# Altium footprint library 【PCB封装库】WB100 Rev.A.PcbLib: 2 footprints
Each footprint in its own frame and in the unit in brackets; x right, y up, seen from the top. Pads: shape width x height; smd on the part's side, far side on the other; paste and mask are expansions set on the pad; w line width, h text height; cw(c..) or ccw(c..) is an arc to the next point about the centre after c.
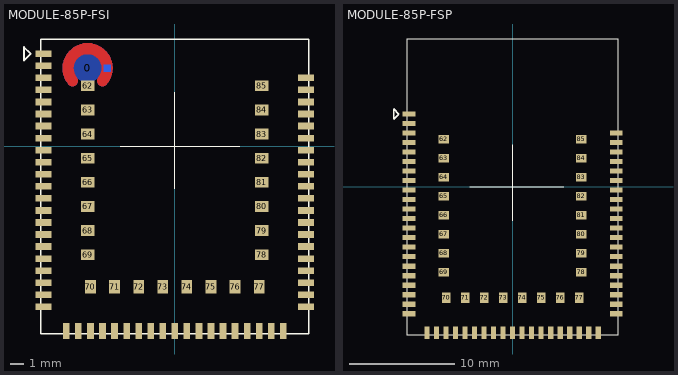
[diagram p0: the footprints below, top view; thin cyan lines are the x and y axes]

## MODULE-85P-FSI [mm]
pads (87):
  round 1.016 on Mech13 paste-0.508 mask+0.152: 0(-6.512,5.818)
  rect 1.2x0.5 smd: 1(-9.8,6.9) 2(-9.8,6) 3(-9.8,5.1) 4(-9.8,4.2) 5(-9.8,3.3) 6(-9.8,2.4) 7(-9.8,1.5) 8(-9.8,0.6) 9(-9.8,-0.3) 10(-9.8,-1.2) 11(-9.8,-2.1) 12(-9.8,-3) 13(-9.8,-3.9) 14(-9.8,-4.8) 15(-9.8,-5.7) 16(-9.8,-6.6) 17(-9.8,-7.5) 18(-9.8,-8.4) 19(-9.8,-9.3) 20(-9.8,-10.2) 21(-9.8,-11.1) 22(-9.8,-12) 42(9.8,-12) 43(9.8,-11.1) 44(9.8,-10.2) 45(9.8,-9.3) 46(9.8,-8.4) 47(9.8,-7.5) 48(9.8,-6.6) 49(9.8,-5.7) 50(9.8,-4.8) 51(9.8,-3.9) 52(9.8,-3) 53(9.8,-2.1) 54(9.8,-1.2) 55(9.8,-0.3) 56(9.8,0.6) 57(9.8,1.5) 58(9.8,2.4) 59(9.8,3.3) 60(9.8,4.2) 61(9.8,5.1)
  rect 0.508x0.508 smd far side paste-0.254: 2(-5.051,5.818)
  rect 0.5x1.2 smd: 23(-8.1,-13.8) 24(-7.2,-13.8) 25(-6.3,-13.8) 26(-5.4,-13.8) 27(-4.5,-13.8) 28(-3.6,-13.8) 29(-2.7,-13.8) 30(-1.8,-13.8) 31(-0.9,-13.8) 32(0,-13.8) 33(0.9,-13.8) 34(1.8,-13.8) 35(2.7,-13.8) 36(3.6,-13.8) 37(4.5,-13.8) 38(5.4,-13.8) 39(6.3,-13.8) 40(7.2,-13.8) 41(8.1,-13.8)
  rect 1x0.8 smd: 62(-6.5,4.5) 63(-6.5,2.7) 64(-6.5,0.9) 65(-6.5,-0.9) 66(-6.5,-2.7) 67(-6.5,-4.5) 68(-6.5,-6.3) 69(-6.5,-8.1) 78(6.5,-8.1) 79(6.5,-6.3) 80(6.5,-4.5) 81(6.5,-2.7) 82(6.5,-0.9) 83(6.5,0.9) 84(6.5,2.7) 85(6.5,4.5)
  rect 0.8x1 smd: 70(-6.3,-10.5) 71(-4.5,-10.5) 72(-2.7,-10.5) 73(-0.9,-10.5) 74(0.9,-10.5) 75(2.7,-10.5) 76(4.5,-10.5) 77(6.3,-10.5)
Top Layer:
  lines w0.838: -7.631,4.879 cw(c-6.512,5.818) -5.393,4.879
Bottom Layer:
  pour cut-out: -7.553,5.818 -7.553,5.921 -7.513,6.122 -7.435,6.311 -7.321,6.482 -7.176,6.627 -7.005,6.741 -6.816,6.819 -6.614,6.859 -6.512,6.859 -6.409,6.859 -6.208,6.819 -6.019,6.741 -5.848,6.627 -5.703,6.482 -5.589,6.311 -5.51,6.122 -5.47,5.921 -5.47,5.818 -5.47,5.716 -5.51,5.514 -5.589,5.325 -5.703,5.154 -5.848,5.009 -6.019,4.895 -6.208,4.817 -6.409,4.777 -6.512,4.777 -6.614,4.777 -6.816,4.817 -7.005,4.895 -7.176,5.009 -7.321,5.154 -7.435,5.325 -7.513,5.514 -7.553,5.716
  lines w0.838: -7.631,4.879 cw(c-6.512,5.818) -5.393,4.879
Top Overlay:
  lines w0.01: -4.059,0 4.846,0 ; 0,-3.195 0,4.011
  lines w0.1: -10,-14 10,-14
  lines w0.102: -10,-14 10,-14 10,8 -10,8 -10,-14
  lines w0.127: -11.268,6.387 -11.268,7.403 -10.76,6.895 -11.268,6.387

## MODULE-85P-FSP [mm]
pads (85):
  rect 1.2x0.5 smd mask-0.25: 1(-9.8,6.9) 2(-9.8,6) 3(-9.8,5.1) 4(-9.8,4.2) 5(-9.8,3.3) 6(-9.8,2.4) 7(-9.8,1.5) 8(-9.8,0.6) 9(-9.8,-0.3) 10(-9.8,-1.2) 11(-9.8,-2.1) 12(-9.8,-3) 13(-9.8,-3.9) 14(-9.8,-4.8) 15(-9.8,-5.7) 16(-9.8,-6.6) 17(-9.8,-7.5) 18(-9.8,-8.4) 19(-9.8,-9.3) 20(-9.8,-10.2) 21(-9.8,-11.1) 22(-9.8,-12) 42(9.8,-12) 43(9.8,-11.1) 44(9.8,-10.2) 45(9.8,-9.3) 46(9.8,-8.4) 47(9.8,-7.5) 48(9.8,-6.6) 49(9.8,-5.7) 50(9.8,-4.8) 51(9.8,-3.9) 52(9.8,-3) 53(9.8,-2.1) 54(9.8,-1.2) 55(9.8,-0.3) 56(9.8,0.6) 57(9.8,1.5) 58(9.8,2.4) 59(9.8,3.3) 60(9.8,4.2) 61(9.8,5.1)
  rect 0.5x1.2 smd mask-0.25: 23(-8.1,-13.8) 24(-7.2,-13.8) 25(-6.3,-13.8) 26(-5.4,-13.8) 27(-4.5,-13.8) 28(-3.6,-13.8) 29(-2.7,-13.8) 30(-1.8,-13.8) 31(-0.9,-13.8) 32(0,-13.8) 33(0.9,-13.8) 34(1.8,-13.8) 35(2.7,-13.8) 36(3.6,-13.8) 37(4.5,-13.8) 38(5.4,-13.8) 39(6.3,-13.8) 40(7.2,-13.8) 41(8.1,-13.8)
  rect 1x0.8 smd: 62(-6.5,4.5) 63(-6.5,2.7) 64(-6.5,0.9) 65(-6.5,-0.9) 66(-6.5,-2.7) 67(-6.5,-4.5) 68(-6.5,-6.3) 69(-6.5,-8.1) 78(6.5,-8.1) 79(6.5,-6.3) 80(6.5,-4.5) 81(6.5,-2.7) 82(6.5,-0.9) 83(6.5,0.9) 84(6.5,2.7) 85(6.5,4.5)
  rect 0.8x1 smd: 70(-6.3,-10.5) 71(-4.5,-10.5) 72(-2.7,-10.5) 73(-0.9,-10.5) 74(0.9,-10.5) 75(2.7,-10.5) 76(4.5,-10.5) 77(6.3,-10.5)
Top Overlay:
  lines w0.01: -4.059,0 4.846,0 ; 0,-3.195 0,4.011
  lines w0.1: -10,-14 -10,14 10,14 10,-14 -10,-14
  lines w0.127: -11.268,6.387 -10.76,6.895 -11.268,7.403 -11.268,6.387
